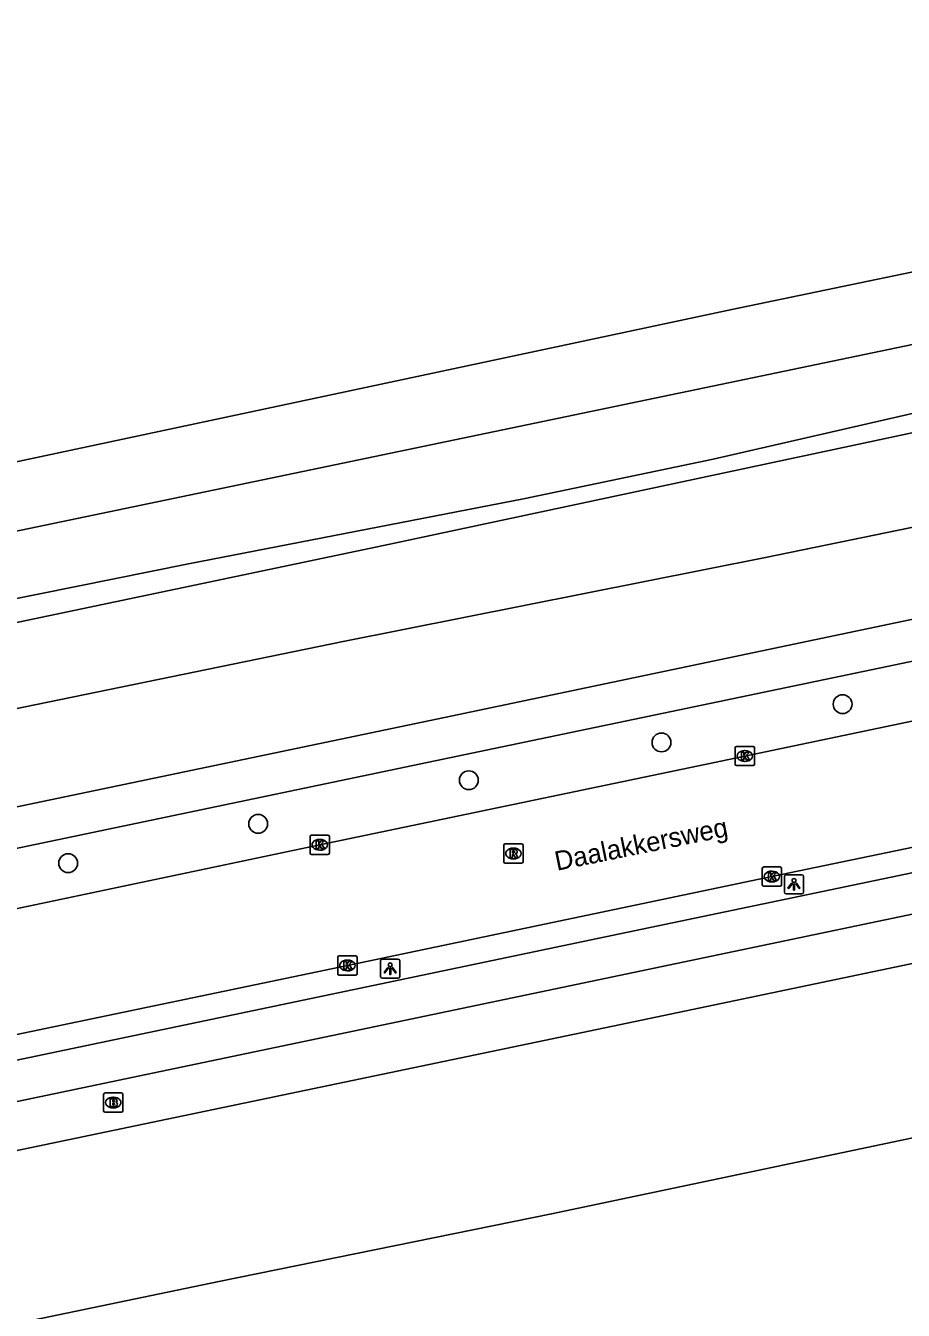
# Model space of a CAD drawing. Extents: x 164494 to 166241, y 382475 to 384494.
# Drawn here: x 165022 to 165067.7, y 384340.2 to 384407 of the extents above; entities that cross this region are included whole.
import ezdxf

# ---------------------------------------------------------------- set-up
doc = ezdxf.new("R2010")
doc.units = 0
for name, color, linetype in [('IMGEO_Boom', 7, 'Continuous'), ('IMGEO_Brandkraan', 7, 'Continuous'), ('IMGEO_Fietspad_open', 7, 'Continuous'), ('IMGEO_Greppel_droge_sloot', 7, 'Continuous'), ('IMGEO_Groenvoorziening', 7, 'Continuous'), ('IMGEO_Hek', 7, 'Continuous'), ('IMGEO_Kolk', 7, 'Continuous'), ('IMGEO_Lichtpunt', 7, 'Continuous'), ('IMGEO_Openbare_ruimte_label', 7, 'Continuous'), ('IMGEO_Rijbaan_lokaal_open', 7, 'Continuous'), ('IMGEO_Rioolput', 7, 'Continuous'), ('IMGEO_Spoor', 7, 'Continuous'), ('IMGEO_Spoorbaan_halfverhard', 7, 'Continuous'), ('IMGEO_Voetpad_open', 7, 'Continuous')]:
    doc.layers.add(name, color=color, linetype=linetype)

msp = doc.modelspace()

# ---------------------------------------------------------------- linework, layer by layer
at = {"layer": 'IMGEO_Boom'}
for centre in [(165064.547, 384371.695), (165055.122, 384369.705), (165045.099, 384367.741), (165034.14, 384365.475), (165024.257, 384363.43)]:
    msp.add_circle(centre, 0.489, dxfattribs=at)
at = {"layer": 'IMGEO_Brandkraan'}
for p, q in [((165026.101, 384350.558), (165026.101, 384351.41)), ((165026.176, 384351.484), (165027.028, 384351.484)), ((165026.589, 384351.264), (165026.614, 384351.264)), ((165027.102, 384351.41), (165027.102, 384350.558)), ((165026.612, 384350.704), (165026.587, 384350.704)), ((165027.028, 384350.484), (165026.176, 384350.484))]:
    msp.add_line(p, q, dxfattribs=at)
for points in [[(165026.101, 384350.558), (165026.101, 384351.41)], [(165026.176, 384351.484), (165027.028, 384351.484)], [(165027.102, 384351.41), (165027.102, 384350.558)], [(165026.449, 384351.184), (165026.449, 384350.784), (165026.662, 384350.784)], [(165026.68, 384351.184), (165026.449, 384351.184)], [(165026.628, 384351.103), (165026.574, 384351.103), (165026.574, 384351.027)], [(165026.574, 384351.027), (165026.627, 384351.027)], [(165026.636, 384350.951), (165026.574, 384350.951), (165026.574, 384350.87)], [(165026.574, 384350.87), (165026.636, 384350.87)], [(165027.028, 384350.484), (165026.176, 384350.484)]]:
    msp.add_lwpolyline(points, dxfattribs=at)
for centre, radius, start, end in [((165026.178, 384351.408), 0.0765, 91.55205, 178.44795), ((165026.178, 384351.408), 0.0765, 91.55205, 178.44795), ((165027.026, 384351.408), 0.0765, 1.55205, 88.44795), ((165027.026, 384351.408), 0.0765, 1.55205, 88.44795), ((165026.178, 384350.56), 0.0765, 181.55205, 268.44795), ((165026.178, 384350.56), 0.0765, 181.55205, 268.44795), ((165026.629, 384351.065), 0.0379, 267.82845, 90.93552), ((165026.637, 384350.91), 0.0404, 269.87594, 90.50774), ((165026.668, 384351.035), 0.251, 268.66757, 293.53466), ((165026.684, 384351.039), 0.145, 59.4692, 91.53667), ((165026.709, 384351.086), 0.0922, 285.51372, 58.15012), ((165026.714, 384350.894), 0.105, 301.31148, 78.98903), ((165027.026, 384350.56), 0.0765, 271.55205, 358.44795), ((165027.026, 384350.56), 0.0765, 271.55205, 358.44795)]:
    msp.add_arc(centre, radius, start, end, dxfattribs=at)
for centre, major_axis, ratio, start_param, end_param in [((165026.588, 384350.984), (-0.387, 0.002), 0.722429, 4.712389, 7.853982), ((165026.613, 384350.984), (-0.39, 0.002), 0.717154, 1.570796, 4.712389)]:
    msp.add_ellipse(centre, major_axis=major_axis, ratio=ratio, start_param=start_param, end_param=end_param, dxfattribs=at)
at = {"layer": 'IMGEO_Fietspad_open'}
for points in [[(165105.349, 384383.872), (165102.387, 384383.258), (165077.784, 384378.116), (165043.832, 384371.007), (165000.08, 384361.873), (164984.803, 384358.696)], [(164926.103, 384341.106), (164925.461, 384344.192), (164936.708, 384346.52), (164998.737, 384359.434), (165044.842, 384369.066), (165078.417, 384376.067), (165103.145, 384381.247)], [(165118.509, 384373.384), (165114.768, 384372.637), (165100.699, 384369.712), (165051.79, 384359.513), (165001.461, 384348.974)], [(165123.59, 384372.323), (165118.614, 384371.278), (165101.155, 384367.679), (165052.181, 384357.436), (165001.876, 384346.919), (164996.584, 384345.814), (164978.743, 384342.085), (164958.923, 384337.938), (164932.507, 384332.46), (164912.329, 384328.255), (164868.92, 384319.253), (164838.611, 384312.969), (164833.08, 384311.822), (164809.925, 384307.04), (164802.068, 384305.407)]]:
    msp.add_lwpolyline(points, dxfattribs=at)
at = {"layer": 'IMGEO_Greppel_droge_sloot'}
for points in [[(165104.993, 384388.454), (165106.065, 384389.82), (165106.003, 384390.697), (165105.583, 384391.703), (165104.253, 384391.797), (165094.853, 384389.829), (165092.786, 384389.521), (165090.64, 384389.08), (165088.711, 384388.988), (165086.738, 384389.38), (165085.335, 384389.341), (165083.775, 384389.121), (165040.998, 384380.02), (165000.91, 384371.603), (164912.198, 384353.222), (164815.807, 384332.872), (164812.064, 384331.961), (164811.065, 384331.621), (164810.561, 384331.362), (164810.234, 384331.045), (164809.929, 384330.437), (164809.818, 384329.948), (164809.989, 384329.284), (164810.161, 384329.041)], [(164983.603, 384364.664), (164999.896, 384367.862), (165017.437, 384370.613), (165038.566, 384374.957), (165060.537, 384379.313), (165104.508, 384388.354)]]:
    msp.add_lwpolyline(points, dxfattribs=at)
at = {"layer": 'IMGEO_Groenvoorziening'}
msp.add_lwpolyline([(165128.463, 384361.866), (165121.194, 384360.319), (165097.67, 384355.369), (165074.224, 384350.422), (165049.402, 384345.197), (165032.09, 384341.677), (165016.726, 384338.497), (165016.804, 384338.097)], dxfattribs=at)
at = {"layer": 'IMGEO_Hek'}
for points in [[(164792.371, 384325.328), (164793.82, 384325.659), (164799.547, 384326.819), (164862.281, 384339.951), (164950.027, 384358.074), (164999.896, 384367.862), (165017.437, 384370.613), (165038.566, 384374.957), (165060.537, 384379.313), (165104.993, 384388.454), (165107.365, 384388.949), (165107.179, 384392.936), (165107.536, 384394.767)], [(165128.694, 384361.62), (165128.463, 384361.866), (165121.194, 384360.319), (165097.67, 384355.369), (165074.224, 384350.422), (165049.402, 384345.197), (165032.09, 384341.677), (165016.726, 384338.497), (165016.804, 384338.097)]]:
    msp.add_lwpolyline(points, dxfattribs=at)
at = {"layer": 'IMGEO_Kolk'}
for p, q in [((165058.958, 384368.573), (165058.958, 384369.425)), ((165059.033, 384369.499), (165059.885, 384369.499)), ((165059.446, 384369.279), (165059.471, 384369.279)), ((165059.959, 384369.425), (165059.959, 384368.573)), ((165059.469, 384368.719), (165059.444, 384368.719)), ((165059.885, 384368.499), (165059.033, 384368.499)), ((165036.845, 384363.957), (165036.845, 384364.809)), ((165036.92, 384364.883), (165037.772, 384364.883)), ((165037.333, 384364.663), (165037.358, 384364.663)), ((165037.846, 384364.809), (165037.846, 384363.957)), ((165037.356, 384364.103), (165037.331, 384364.103)), ((165037.772, 384363.883), (165036.92, 384363.883)), ((165060.365, 384362.308), (165060.365, 384363.16)), ((165060.44, 384363.234), (165061.292, 384363.234)), ((165060.853, 384363.014), (165060.878, 384363.014)), ((165061.366, 384363.16), (165061.366, 384362.308)), ((165061.292, 384362.234), (165060.44, 384362.234)), ((165060.876, 384362.454), (165060.851, 384362.454)), ((165038.36, 384358.61), (165039.212, 384358.61)), ((165038.285, 384357.684), (165038.285, 384358.536)), ((165038.773, 384358.39), (165038.798, 384358.39)), ((165039.286, 384358.536), (165039.286, 384357.684)), ((165039.212, 384357.61), (165038.36, 384357.61)), ((165038.796, 384357.83), (165038.771, 384357.83))]:
    msp.add_line(p, q, dxfattribs=at)
for points in [[(165058.958, 384368.573), (165058.958, 384369.425)], [(165059.033, 384369.499), (165059.885, 384369.499)], [(165059.959, 384369.425), (165059.959, 384368.573)], [(165059.279, 384369.199), (165059.402, 384369.199), (165059.402, 384369.048), (165059.532, 384369.199), (165059.696, 384369.199), (165059.55, 384369.048), (165059.703, 384368.799), (165059.551, 384368.799), (165059.466, 384368.963), (165059.402, 384368.896), (165059.402, 384368.799), (165059.279, 384368.799), (165059.279, 384369.199)], [(165059.885, 384368.499), (165059.033, 384368.499)], [(165036.845, 384363.957), (165036.845, 384364.809)], [(165036.92, 384364.883), (165037.772, 384364.883)], [(165037.166, 384364.583), (165037.289, 384364.583), (165037.289, 384364.432), (165037.419, 384364.583), (165037.583, 384364.583), (165037.437, 384364.432), (165037.59, 384364.183), (165037.438, 384364.183), (165037.353, 384364.347), (165037.289, 384364.28), (165037.289, 384364.183), (165037.166, 384364.183), (165037.166, 384364.583)], [(165037.846, 384364.809), (165037.846, 384363.957)], [(165037.772, 384363.883), (165036.92, 384363.883)], [(165060.365, 384362.308), (165060.365, 384363.16)], [(165060.44, 384363.234), (165061.292, 384363.234)], [(165060.686, 384362.934), (165060.809, 384362.934), (165060.809, 384362.783), (165060.939, 384362.934), (165061.103, 384362.934), (165060.957, 384362.783), (165061.11, 384362.534), (165060.958, 384362.534), (165060.873, 384362.698), (165060.809, 384362.631), (165060.809, 384362.534), (165060.686, 384362.534), (165060.686, 384362.934)], [(165061.366, 384363.16), (165061.366, 384362.308)], [(165061.292, 384362.234), (165060.44, 384362.234)], [(165038.36, 384358.61), (165039.212, 384358.61)], [(165038.285, 384357.684), (165038.285, 384358.536)], [(165038.606, 384358.31), (165038.729, 384358.31), (165038.729, 384358.159), (165038.859, 384358.31), (165039.023, 384358.31), (165038.877, 384358.159), (165039.03, 384357.91), (165038.878, 384357.91), (165038.793, 384358.074), (165038.729, 384358.007), (165038.729, 384357.91), (165038.606, 384357.91), (165038.606, 384358.31)], [(165039.286, 384358.536), (165039.286, 384357.684)], [(165039.212, 384357.61), (165038.36, 384357.61)]]:
    msp.add_lwpolyline(points, dxfattribs=at)
for centre, start, end in [((165059.035, 384369.423), 91.55205, 178.44795), ((165059.035, 384369.423), 91.55205, 178.44795), ((165059.883, 384369.423), 1.55205, 88.44795), ((165059.883, 384369.423), 1.55205, 88.44795), ((165059.035, 384368.575), 181.55205, 268.44795), ((165059.035, 384368.575), 181.55205, 268.44795), ((165059.883, 384368.575), 271.55205, 358.44795), ((165059.883, 384368.575), 271.55205, 358.44795), ((165036.922, 384364.807), 91.55205, 178.44795), ((165036.922, 384364.807), 91.55205, 178.44795), ((165037.77, 384364.807), 1.55205, 88.44795), ((165037.77, 384364.807), 1.55205, 88.44795), ((165036.922, 384363.959), 181.55205, 268.44795), ((165036.922, 384363.959), 181.55205, 268.44795), ((165037.77, 384363.959), 271.55205, 358.44795), ((165037.77, 384363.959), 271.55205, 358.44795), ((165060.442, 384363.158), 91.55205, 178.44795), ((165060.442, 384363.158), 91.55205, 178.44795), ((165061.29, 384363.158), 1.55205, 88.44795), ((165061.29, 384363.158), 1.55205, 88.44795), ((165060.442, 384362.31), 181.55205, 268.44795), ((165060.442, 384362.31), 181.55205, 268.44795), ((165061.29, 384362.31), 271.55205, 358.44795), ((165061.29, 384362.31), 271.55205, 358.44795), ((165038.362, 384358.534), 91.55205, 178.44795), ((165038.362, 384358.534), 91.55205, 178.44795), ((165039.21, 384358.534), 1.55205, 88.44795), ((165039.21, 384358.534), 1.55205, 88.44795), ((165038.362, 384357.686), 181.55205, 268.44795), ((165038.362, 384357.686), 181.55205, 268.44795), ((165039.21, 384357.686), 271.55205, 358.44795), ((165039.21, 384357.686), 271.55205, 358.44795)]:
    msp.add_arc(centre, 0.0765, start, end, dxfattribs=at)
for centre, major_axis, ratio, start_param, end_param in [((165059.445, 384368.999), (-0.387, 0.002), 0.722429, 4.712389, 7.853982), ((165059.47, 384368.999), (-0.39, 0.002), 0.717154, 1.570796, 4.712389), ((165037.332, 384364.383), (-0.387, 0.002), 0.722429, 4.712389, 7.853982), ((165037.357, 384364.383), (-0.39, 0.002), 0.717154, 1.570796, 4.712389), ((165060.852, 384362.734), (-0.387, 0.002), 0.722429, 4.712389, 7.853982), ((165060.877, 384362.734), (-0.39, 0.002), 0.717154, 1.570796, 4.712389), ((165038.772, 384358.11), (-0.387, 0.002), 0.722429, 4.712389, 7.853982), ((165038.797, 384358.11), (-0.39, 0.002), 0.717154, 1.570796, 4.712389)]:
    msp.add_ellipse(centre, major_axis=major_axis, ratio=ratio, start_param=start_param, end_param=end_param, dxfattribs=at)
at = {"layer": 'IMGEO_Lichtpunt'}
for p, q in [((165061.518, 384362.732), (165061.518, 384361.925)), ((165061.518, 384362.732), (165061.518, 384361.925)), ((165062.42, 384362.827), (165061.612, 384362.827)), ((165062.42, 384362.827), (165061.612, 384362.827)), ((165062.514, 384361.925), (165062.514, 384362.732)), ((165062.514, 384361.925), (165062.514, 384362.732)), ((165061.612, 384361.831), (165062.42, 384361.831)), ((165061.612, 384361.831), (165062.42, 384361.831)), ((165040.512, 384358.348), (165040.512, 384357.541)), ((165040.512, 384358.348), (165040.512, 384357.541)), ((165041.414, 384358.443), (165040.606, 384358.443)), ((165041.414, 384358.443), (165040.606, 384358.443)), ((165041.508, 384357.541), (165041.508, 384358.348)), ((165041.508, 384357.541), (165041.508, 384358.348)), ((165040.606, 384357.447), (165041.414, 384357.447)), ((165040.606, 384357.447), (165041.414, 384357.447))]:
    msp.add_line(p, q, dxfattribs=at)
for points in [[(165061.892, 384362.396), (165061.931, 384362.368), (165061.743, 384362.106), (165061.705, 384362.133), (165061.892, 384362.396)], [(165061.994, 384362.348), (165062.041, 384362.348), (165062.041, 384362.026), (165061.994, 384362.026), (165061.994, 384362.348)], [(165062.104, 384362.368), (165062.142, 384362.395), (165062.329, 384362.133), (165062.29, 384362.105), (165062.104, 384362.368)], [(165040.886, 384358.012), (165040.925, 384357.984), (165040.737, 384357.722), (165040.699, 384357.749), (165040.886, 384358.012)], [(165040.988, 384357.964), (165041.035, 384357.964), (165041.035, 384357.642), (165040.988, 384357.642), (165040.988, 384357.964)], [(165041.098, 384357.984), (165041.136, 384358.011), (165041.323, 384357.749), (165041.284, 384357.721), (165041.098, 384357.984)]]:
    msp.add_lwpolyline(points, dxfattribs=at)
for centre in [(165062.017, 384362.53), (165041.011, 384358.146)]:
    msp.add_circle(centre, 0.0994, dxfattribs=at)
for centre, start, end in [((165061.612, 384362.732), 90, 180), ((165061.612, 384362.732), 90, 180), ((165062.42, 384362.732), 0, 90), ((165062.42, 384362.732), 0, 90), ((165061.612, 384361.925), 180, 270), ((165061.612, 384361.925), 180, 270), ((165062.42, 384361.925), 270, 0), ((165062.42, 384361.925), 270, 360), ((165040.606, 384358.348), 90, 180), ((165040.606, 384358.348), 90, 180), ((165041.414, 384358.348), 0, 90), ((165041.414, 384358.348), 0, 90), ((165040.606, 384357.541), 180, 270), ((165040.606, 384357.541), 180, 270), ((165041.414, 384357.541), 270, 0), ((165041.414, 384357.541), 270, 360)]:
    msp.add_arc(centre, 0.0946, start, end, dxfattribs=at)
at = {"layer": 'IMGEO_Rijbaan_lokaal_open'}
for points in [[(165103.841, 384378.298), (165103.18, 384378.131), (165082.552, 384373.828), (165059.459, 384368.999), (165037.346, 384364.383), (165015.253, 384359.737), (164994.137, 384355.385), (164980.37, 384352.43), (164954.306, 384347.035), (164933.216, 384342.574), (164926.103, 384341.106)], [(165001.186, 384350.268), (165016.662, 384353.497), (165038.786, 384358.11), (165060.866, 384362.734), (165083.93, 384367.513), (165118.108, 384374.601)]]:
    msp.add_lwpolyline(points, dxfattribs=at)
at = {"layer": 'IMGEO_Rioolput'}
for p, q in [((165046.918, 384363.505), (165046.918, 384364.357)), ((165046.993, 384364.431), (165047.845, 384364.431)), ((165047.406, 384364.211), (165047.431, 384364.211)), ((165047.919, 384364.357), (165047.919, 384363.505)), ((165047.845, 384363.431), (165046.993, 384363.431)), ((165047.429, 384363.651), (165047.404, 384363.651))]:
    msp.add_line(p, q, dxfattribs=at)
for points in [[(165046.918, 384363.505), (165046.918, 384364.357)], [(165046.993, 384364.431), (165047.845, 384364.431)], [(165047.507, 384364.129), (165047.255, 384364.131), (165047.255, 384363.731)], [(165047.433, 384364.05), (165047.379, 384364.05), (165047.379, 384363.969)], [(165047.379, 384363.969), (165047.431, 384363.969)], [(165047.919, 384364.357), (165047.919, 384363.505)], [(165047.845, 384363.431), (165046.993, 384363.431)], [(165047.255, 384363.731), (165047.379, 384363.731), (165047.379, 384363.893), (165047.39, 384363.893)], [(165047.437, 384363.864), (165047.508, 384363.731), (165047.648, 384363.731), (165047.583, 384363.857)]]:
    msp.add_lwpolyline(points, dxfattribs=at)
for centre, radius, start, end in [((165046.995, 384364.355), 0.0765, 91.55205, 178.44795), ((165046.995, 384364.355), 0.0765, 91.55205, 178.44795), ((165047.415, 384364.158), 0.19, 274.7715, 282.96867), ((165047.439, 384363.954), 0.0964, 77.00612, 93.18647), ((165047.453, 384364.011), 0.0378, 276.66336, 79.67722), ((165047.506, 384364.019), 0.109, 350.36119, 89.41601), ((165047.504, 384364.019), 0.112, 277.58423, 350.98172), ((165047.843, 384364.355), 0.0765, 1.55205, 88.44795), ((165047.843, 384364.355), 0.0765, 1.55205, 88.44795), ((165046.995, 384363.507), 0.0765, 181.55205, 268.44795), ((165046.995, 384363.507), 0.0765, 181.55205, 268.44795), ((165047.389, 384363.84), 0.0533, 26.02933, 88.69889), ((165047.488, 384363.804), 0.108, 29.51342, 73.79051), ((165047.843, 384363.507), 0.0765, 271.55205, 358.44795), ((165047.843, 384363.507), 0.0765, 271.55205, 358.44795)]:
    msp.add_arc(centre, radius, start, end, dxfattribs=at)
for centre, major_axis, ratio, start_param, end_param in [((165047.405, 384363.931), (-0.387, 0.002), 0.722429, 4.712389, 7.853982), ((165047.43, 384363.931), (-0.39, 0.002), 0.717154, 1.570796, 4.712389)]:
    msp.add_ellipse(centre, major_axis=major_axis, ratio=ratio, start_param=start_param, end_param=end_param, dxfattribs=at)
at = {"layer": 'IMGEO_Spoor'}
for points in [[(165534.642, 384491.339), (165527.155, 384489.842), (165498.336, 384483.749), (165300.848, 384442.555), (165180.102, 384417.538), (165154.253, 384412.052), (165058.779, 384392.205), (165020.911, 384384.156), (164953.473, 384370.243), (164918.38, 384362.867), (164827.656, 384344.031), (164796.154, 384337.413), (164788.231, 384335.773)], [(165535.404, 384487.554), (165347.592, 384448.533), (165284.368, 384435.3), (165189.312, 384415.622), (165019.715, 384380.308), (164986.051, 384373.23), (164945.984, 384364.945), (164850.572, 384344.992), (164797.73, 384334.115), (164789.572, 384332.389)]]:
    msp.add_lwpolyline(points, dxfattribs=at)
at = {"layer": 'IMGEO_Spoorbaan_halfverhard'}
msp.add_lwpolyline([(164796.468, 384328.762), (164809.794, 384332.027), (164812.313, 384333.001), (164815.919, 384334.01), (164826.252, 384336.209), (164847.742, 384340.431), (164860.86, 384343.215), (164877.535, 384347.017), (164920.34, 384355.646), (164963.792, 384364.777), (164989.47, 384369.926), (164993.61, 384371.368), (165009.016, 384374.65), (165030.52, 384378.991), (165047.947, 384382.37), (165057.819, 384384.438), (165069.605, 384387.142), (165081.406, 384389.702), (165082.707, 384390.536), (165089.022, 384391.879)], dxfattribs=at)
at = {"layer": 'IMGEO_Voetpad_open'}
msp.add_lwpolyline([(165007.446, 384345.541), (165052.6, 384354.959), (165101.82, 384365.255), (165121.469, 384369.317)], dxfattribs=at)

# ---------------------------------------------------------------- texts
at = {"layer": 'IMGEO_Openbare_ruimte_label'}
msp.add_text('Daalakkersweg', height=1, rotation=11.42232, dxfattribs=at).set_placement((165049.682, 384363.03))

doc.saveas('drawing.dxf')
